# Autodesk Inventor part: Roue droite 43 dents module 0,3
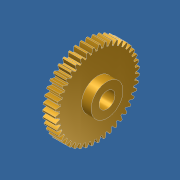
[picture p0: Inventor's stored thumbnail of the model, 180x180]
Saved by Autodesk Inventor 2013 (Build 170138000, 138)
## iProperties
Created: 2011-10
Part Number: Roue droite 43 dents module 0,3
Document SubType Name: Modeling
Designer: Laur
Density: 1 g/cm^3
Material: Générique
Author: Laur
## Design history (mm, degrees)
derived "roue droite de vis arbrée.iam"
node "Solide1"
node "Corps solides"
node "Corps surfaciques"
node "roue droite sur vis arbrée.ipt:1" dims "d0" = 10
node "Engrenages cylindriques:1::Engrenage cylindrique2:1" dims "d0" = 10
